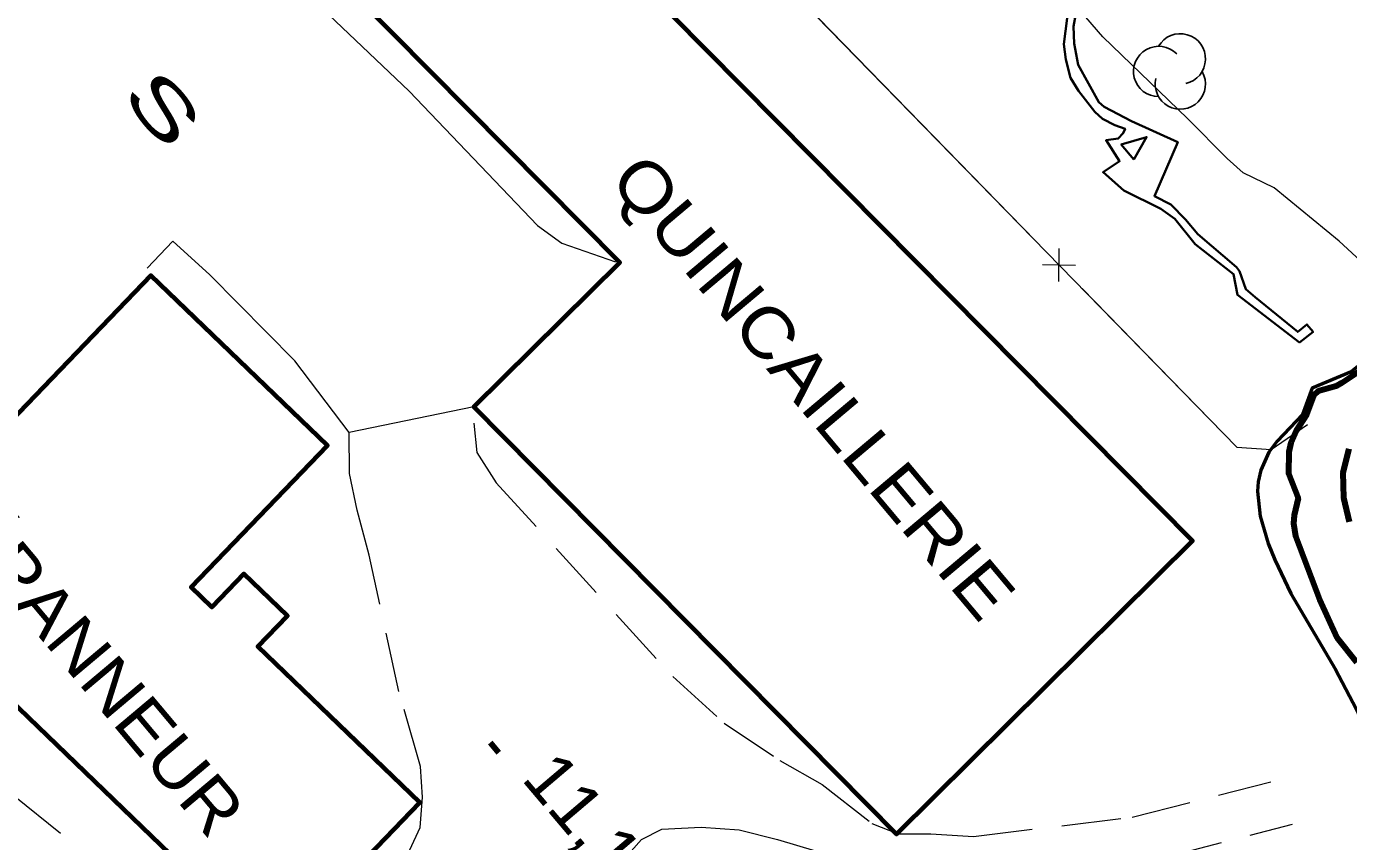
# Model space of a CAD drawing. Extents: x 386081 to 389416, y 5130568 to 5134082.
# Drawn here: x 387094 to 387174.2, y 5131941 to 5131990.4 of the extents above; entities that cross this region are included whole.
import ezdxf
from ezdxf.enums import TextEntityAlignment as Align

# ---------------------------------------------------------------- set-up
doc = ezdxf.new("R2010")
doc.units = 0
doc.header["$LTSCALE"] = 1.2
doc.linetypes.add('DASH_DOUBLE_DOT', pattern=[9.2, 5, -1.2, 0.3, -1.2, 0.3, -1.2])
doc.linetypes.add('MEDIUM_DASHED', pattern=[4.5, 3, -1.5])
for name, color, linetype, lineweight in [('1', 7, 'Continuous', 53), ('19', 7, 'Continuous', 13), ('2', 7, 'Continuous', 13), ('22', 7, 'Continuous', 13), ('3', 7, 'Continuous', 140), ('31', 7, 'Continuous', 70), ('37', 7, 'Continuous', 13), ('4', 7, 'DASH_DOUBLE_DOT', 53), ('44', 7, 'Continuous', 25), ('52', 7, 'Continuous', 13)]:
    doc.layers.add(name, color=color, linetype=linetype, lineweight=lineweight)

msp = doc.modelspace()

# ---------------------------------------------------------------- linework, layer by layer
at = {"layer": '1'}
msp.add_lwpolyline([(387178.67, 5131972.71), (387177.79, 5131972.26), (387174.31, 5131969.45), (387171.94, 5131968.46), (387171.37, 5131966.88), (387169.83, 5131965.26), (387169.32, 5131964.59), (387168.83, 5131963.5), (387168.68, 5131962.8), (387168.64, 5131962.23), (387168.8, 5131960.72), (387169.28, 5131959.05), (387169.69, 5131958.07), (387170.65, 5131956.03), (387173.34, 5131951.46), (387174.64, 5131949.01), (387175.69, 5131946.69), (387176.39, 5131944.71), (387176.56, 5131943.88), (387176.51, 5131942.74), (387176.32, 5131942.19), (387176, 5131941.62), (387175.57, 5131941.05), (387175.03, 5131940.55)], dxfattribs=at)
at = {"layer": '19', "linetype": 'MEDIUM_DASHED'}
for points in [[(387121.13, 5131966.34), (387121.31, 5131964.57), (387122.49, 5131962.74), (387133.19, 5131950.99), (387136.31, 5131948.17), (387139.67, 5131945.92), (387142.25, 5131944.46), (387145.26, 5131942.1), (387146.85, 5131941.47), (387148.83, 5131941.46), (387151.41, 5131941.31), (387161.04, 5131942.47), (387169.44, 5131944.62)], [(387080.86, 5131953.93), (387082.37, 5131952.33), (387084.45, 5131950.47), (387093.27, 5131943.76), (387099.14, 5131939.04), (387102.33, 5131936.31), (387103.68, 5131935.44), (387105.51, 5131934.07), (387106.5, 5131933.57), (387107.48, 5131933.32), (387108.59, 5131933.19), (387109.7, 5131933.3), (387111.3, 5131933.9), (387116.38, 5131938.91), (387117.25, 5131940.5), (387117.88, 5131941.85), (387118.01, 5131943.69), (387117.9, 5131945.54), (387116.58, 5131950.1), (387114.78, 5131958.36), (387114.06, 5131961.07), (387113.58, 5131963.29), (387113.57, 5131965.79)], [(387114.62, 5131919.84), (387113.76, 5131921.38), (387113.75, 5131922.12), (387114.24, 5131923.19), (387115.54, 5131924.51), (387118.31, 5131927), (387122.27, 5131930.75), (387123.65, 5131931.79), (387126.22, 5131933.55), (387128.08, 5131935.59), (387129.25, 5131938.58), (387130.2, 5131939.9), (387131.3, 5131941.13), (387132.53, 5131941.75), (387134.9, 5131941.88), (387137.21, 5131941.71), (387139.54, 5131941.13), (387146.26, 5131939.11), (387148.49, 5131938.33), (387150.75, 5131937.78), (387153.34, 5131938.13), (387157.53, 5131938.84), (387162.97, 5131940.03), (387170.75, 5131942.06)]]:
    msp.add_lwpolyline(points, dxfattribs=at)
at = {"layer": '2'}
msp.add_lwpolyline([(387181.72, 5131978.95), (387179.89, 5131977.51), (387176.33, 5131975.55), (387175.7, 5131975.63), (387174.87, 5131976.18), (387173.58, 5131977.37), (387169.65, 5131980.6), (387167.77, 5131981.52), (387166.79, 5131982.39), (387164.4, 5131984.8), (387159.26, 5131989.76), (387158.22, 5131990.94), (387156.27, 5131993.53), (387156.25, 5131993.75)], dxfattribs=at)
at = {"layer": '22', "lineweight": 35}
msp.add_lwpolyline([(387158.05, 5131993.47), (387157.48, 5131990.38), (387157.53, 5131989.34), (387157.76, 5131988.05), (387159.01, 5131985.79), (387159.33, 5131985.51), (387161, 5131984.65), (387163.8, 5131983.38), (387162.39, 5131980.11), (387163.38, 5131979.59), (387164.28, 5131978.69), (387165.02, 5131977.79), (387167.37, 5131975.8), (387167.54, 5131975.55), (387167.92, 5131974.47), (387168.49, 5131973.98), (387171.07, 5131971.88), (387171.63, 5131972.33), (387172, 5131971.88), (387171.18, 5131971.24), (387167.43, 5131974.12), (387167.17, 5131975.38), (387164.85, 5131977.2), (387163.62, 5131978.72), (387162.77, 5131979.34), (387160.54, 5131980.45), (387159.27, 5131981.55), (387160.27, 5131982.22), (387159.46, 5131983.49), (387160.19, 5131983.59), (387160.5, 5131983.92), (387160.61, 5131984.19), (387159.99, 5131984.4), (387159.24, 5131984.78), (387158.77, 5131985.22), (387157.79, 5131986.48), (387157.29, 5131987.28), (387157.01, 5131988.38), (387156.9, 5131989.3), (387157.43, 5131993.59)], dxfattribs=at)
msp.add_lwpolyline([(387161.13, 5131982.32), (387160.37, 5131983.24), (387161.91, 5131983.68)], close=True, dxfattribs=at)
at = {"layer": '3'}
msp.add_line((387122.12, 5131947), (387122.63, 5131946.39), dxfattribs=at)
at = {"layer": '31'}
for points in [[(387118.4, 5132005.95), (387164.69, 5131959.21), (387146.76, 5131941.45), (387121.13, 5131967.33), (387129.97, 5131976.08), (387109.31, 5131996.94)], [(387086.47, 5131968.73), (387081.87, 5131963.95), (387086.47, 5131959.53), (387083.09, 5131956.01), (387089.67, 5131949.67), (387091.23, 5131951.28), (387109.01, 5131934.17), (387117.86, 5131943.37), (387108.04, 5131952.81), (387109.84, 5131954.68), (387107.19, 5131957.22), (387105.25, 5131955.21), (387103.99, 5131956.42), (387112.25, 5131965), (387101.54, 5131975.3), (387091.02, 5131964.36)]]:
    msp.add_lwpolyline(points, close=True, dxfattribs=at)
at = {"layer": '37'}
for p, q in [((387141.23, 5131991.69), (387148.22, 5131984.53)), ((387148.22, 5131984.53), (387155.2, 5131977.37)), ((387156.59, 5131974.94), (387156.61, 5131976.94)), ((387155.6, 5131975.96), (387157.6, 5131975.93)), ((387158, 5131974.51), (387164.98, 5131967.36))]:
    msp.add_line(p, q, dxfattribs=at)
for points in [[(387114.69, 5132018.88), (387167.38, 5131964.9), (387169.47, 5131964.75), (387171.67, 5131966.26)], [(387164.98, 5131967.36), (387167.38, 5131964.9), (387169.47, 5131964.75), (387171.67, 5131966.26)]]:
    msp.add_lwpolyline(points, dxfattribs=at)
at = {"layer": '4', "linetype": 'Continuous', "lineweight": 90}
for points in [[(387175.62, 5131970.05), (387173.75, 5131968.79), (387173.41, 5131968.59), (387172.31, 5131968.28), (387172.06, 5131968.05), (387171.6, 5131966.86), (387170.97, 5131965.88), (387170.66, 5131965.15), (387170.53, 5131964.62), (387170.51, 5131963.3), (387171.1, 5131961.8), (387170.86, 5131960.78), (387170.82, 5131960.26), (387170.94, 5131959.51), (387172.4, 5131955.67), (387173.45, 5131953.36), (387174.63, 5131951.86)], [(387174.21, 5131960.37), (387173.86, 5131961.82), (387173.83, 5131963.36), (387174.2, 5131964.8)]]:
    msp.add_lwpolyline(points, dxfattribs=at)
at = {"layer": '44'}
for centre, start, end in [((387163.957, 5131988.418), 282.26917, 149.72626), ((387162.645, 5131987.655), 44.11537, 269.80396), ((387163.957, 5131986.892), 166.93686, 29.62122)]:
    msp.add_arc(centre, 1.526, start, end, dxfattribs=at)
at = {"layer": '52'}
msp.add_line((387101.33, 5131975.74), (387102.87, 5131977.37), dxfattribs=at)
for points in [[(387099.29, 5131993.75), (387101.14, 5131994.25), (387104.63, 5131993.91), (387106.72, 5131993.25), (387109.45, 5131992.68), (387111.03, 5131992.05), (387112.33, 5131991.08), (387117.2, 5131986.46), (387124.98, 5131978.33), (387126.46, 5131977.26), (387129.72, 5131976.13)], [(387121.13, 5131967.33), (387113.57, 5131965.79), (387110.27, 5131970.12), (387105.13, 5131975.33), (387102.87, 5131977.37)]]:
    msp.add_lwpolyline(points, dxfattribs=at)

# ---------------------------------------------------------------- texts
at = {"layer": '3', "width": 1.05}
msp.add_text('11,1   ', height=3, rotation=310.294, dxfattribs=at).set_placement((387123.95, 5131944.78))
at = {"layer": '31'}
for s, width, p in [('QUINCAILLERIE', 1.15, (387129.26, 5131981.03)), ('DÉPANNEUR', 1.1, (387087.31, 5131962.26))]:
    msp.add_text(s, height=3, rotation=310.03, dxfattribs=dict(at, width=width)).set_placement(p)
at = {"layer": '52', "width": 1.7}
msp.add_text('S', height=3, rotation=310.03, dxfattribs=at).set_placement((387101.14, 5131984.45), align=Align.CENTER)

doc.saveas('drawing.dxf')
